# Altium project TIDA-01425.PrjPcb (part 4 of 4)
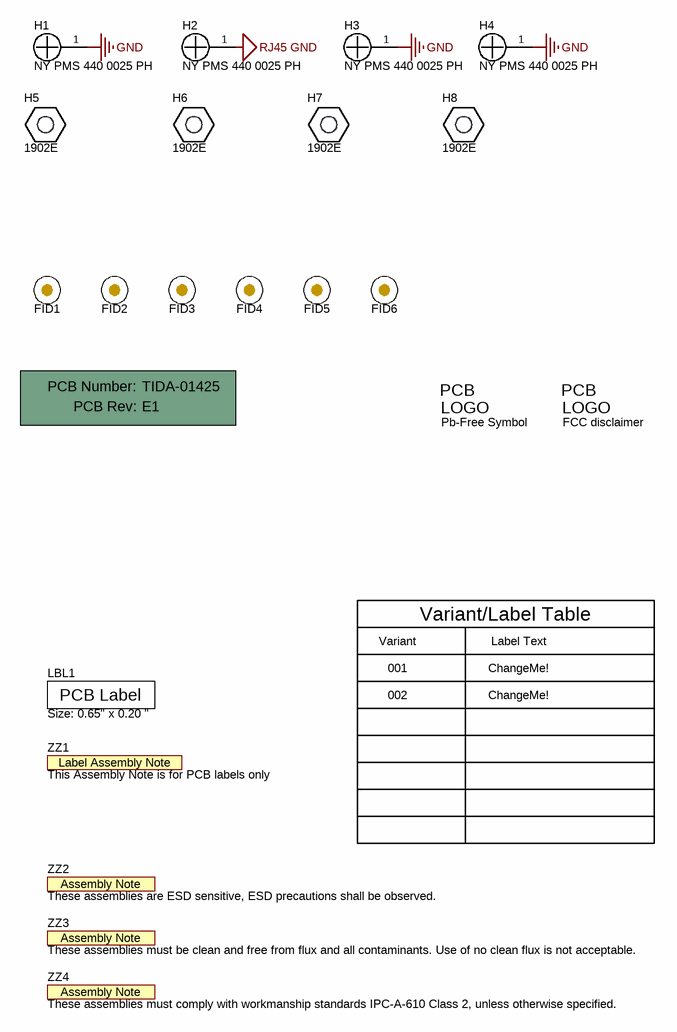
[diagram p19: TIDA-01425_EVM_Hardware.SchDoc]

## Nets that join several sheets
GND: DCDC PWR (37 pins), LP873x (PMIC) (47 pins), ANA PWR (40 pins), DIG PWR (148 pins), J6Entry (26 pins), J6E DDR (16 pins), DDR3 (74 pins), Ethernet_subsystem (48 pins), CAN_subsystem2.0 (24 pins), JTAG (9 pins), TIDA-01425_EVM_Hardware (H1.1 H3.1 H4.1)
RJ45 GND: Ethernet_subsystem (7 pins), TIDA-01425_EVM_Hardware (H2.1)
VDDS_1V8: LP873x (PMIC) (6 pins), DIG PWR (25 pins), J6Entry (U12.3)
BOARD_12V: DCDC PWR (12 pins), CAN_subsystem2.0 (J1.9)
DCAN1_RX: J6Entry (U13.H23), CAN_subsystem2.0 (CAN1_RX.1 U1.4 U3.4)
DCAN1_STB: J6Entry (U13.Y6), CAN_subsystem2.0 (R4.2)
DCAN1_TX: J6Entry (U13.H22), CAN_subsystem2.0 (CAN1_TX.1 U1.1 U3.1)
DCAN2_RX: J6Entry (U13.K22), CAN_subsystem2.0 (CAN2_RX.1 U2.4 U3.7)
DCAN2_STB: J6Entry (U13.K23), CAN_subsystem2.0 (R8.2)
DCAN2_TX: J6Entry (U13.H21), CAN_subsystem2.0 (CAN2_TX.1 U2.1 U3.6)
DDR EN: LP873x (PMIC) (R145.1 TP63.1 U26.10), J6E DDR (R69.2)
EMU_RSTn: J6Entry (R114.1), JTAG (J4.6 R52.1)
ENET_EN: J6Entry (U13.H5), Ethernet_subsystem (R34.2 U9.7)
ENET_INH: J6Entry (U13.G6), Ethernet_subsystem (U9.10)
ENET_INTSn: J6Entry (U13.L4), Ethernet_subsystem (U9.2)
ENET_WAKE: J6Entry (U13.G5), Ethernet_subsystem (R35.2 U9.8)
ETH_CLK0: J6Entry (R1.2), Ethernet_subsystem (U5.28)
ETH_CLK1: J6Entry (R19.2), Ethernet_subsystem (U9.5)
H_DDR1_A0: J6E DDR (R67.1 U13.AC18), DDR3 (U14.N3 U15.N3)
H_DDR1_A1: J6E DDR (R68.1 U13.AE19), DDR3 (U14.P7 U15.P7)
H_DDR1_A2: J6E DDR (R71.1 U13.AD19), DDR3 (U14.P3 U15.P3)
H_DDR1_A3: J6E DDR (R72.1 U13.AB19), DDR3 (U14.N2 U15.N2)
H_DDR1_A4: J6E DDR (R74.1 U13.AD20), DDR3 (U14.P8 U15.P8)
H_DDR1_A5: J6E DDR (R76.1 U13.AE20), DDR3 (U14.P2 U15.P2)
H_DDR1_A6: J6E DDR (R77.1 U13.AA18), DDR3 (U14.R8 U15.R8)
H_DDR1_A7: J6E DDR (R78.1 U13.AA20), DDR3 (U14.R2 U15.R2)
H_DDR1_A8: J6E DDR (R80.1 U13.Y21), DDR3 (U14.T8 U15.T8)
H_DDR1_A9: J6E DDR (R81.1 U13.AC20), DDR3 (U14.R3 U15.R3)
H_DDR1_A10: J6E DDR (R82.1 U13.AA21), DDR3 (U14.L7 U15.L7)
H_DDR1_A11: J6E DDR (R83.1 U13.AC21), DDR3 (U14.R7 U15.R7)
H_DDR1_A12: J6E DDR (R84.1 U13.AC22), DDR3 (U14.N7 U15.N7)
H_DDR1_BA0: J6E DDR (R85.1 U13.AE16), DDR3 (U14.M2 U15.M2)
H_DDR1_BA1: J6E DDR (R86.1 U13.AA16), DDR3 (U14.N8 U15.N8)
H_DDR1_BA2: J6E DDR (R87.1 U13.AB16), DDR3 (U14.M3 U15.M3)
H_DDR1_CASN: J6E DDR (R65.2 U13.AD16), DDR3 (U14.K3 U15.K3)
H_DDR1_CKE: J6E DDR (R62.1 U13.AB18), DDR3 (U14.K9 U15.K9)
H_DDR1_CLK_N: J6E DDR (R90.1 U13.AE21), DDR3 (U14.K7 U15.K7)
H_DDR1_CLK_P: J6E DDR (R89.1 U13.AD21), DDR3 (U14.J7 U15.J7)
H_DDR1_CSN0: J6E DDR (R63.1 U13.AC19), DDR3 (U14.L2 U15.L2)
H_DDR1_D0: J6E DDR (U13.AA23), DDR3 (U14.H7)
H_DDR1_D1: J6E DDR (U13.AC24), DDR3 (U14.F8)
H_DDR1_D2: J6E DDR (U13.AB24), DDR3 (U14.F7)
H_DDR1_D3: J6E DDR (U13.AD24), DDR3 (U14.H8)
H_DDR1_D4: J6E DDR (U13.AB23), DDR3 (U14.E3)
H_DDR1_D5: J6E DDR (U13.AC23), DDR3 (U14.H3)
H_DDR1_D6: J6E DDR (U13.AD23), DDR3 (U14.F2)
H_DDR1_D7: J6E DDR (U13.AE24), DDR3 (U14.G2)
H_DDR1_D8: J6E DDR (U13.AA24), DDR3 (U14.A2)
H_DDR1_D9: J6E DDR (U13.W25), DDR3 (U14.B8)
H_DDR1_D10: J6E DDR (U13.Y23), DDR3 (U14.A7)
H_DDR1_D11: J6E DDR (U13.AD25), DDR3 (U14.C8)
H_DDR1_D12: J6E DDR (U13.AC25), DDR3 (U14.C3)
H_DDR1_D13: J6E DDR (U13.AB25), DDR3 (U14.D7)
H_DDR1_D14: J6E DDR (U13.AA25), DDR3 (U14.A3)
H_DDR1_D15: J6E DDR (U13.W24), DDR3 (U14.C2)
H_DDR1_D16: J6E DDR (U13.W23), DDR3 (U15.F8)
H_DDR1_D17: J6E DDR (U13.U25), DDR3 (U15.H8)
H_DDR1_D18: J6E DDR (U13.U24), DDR3 (U15.F7)
H_DDR1_D19: J6E DDR (U13.W21), DDR3 (U15.F2)
H_DDR1_D20: J6E DDR (U13.T22), DDR3 (U15.E3)
H_DDR1_D21: J6E DDR (U13.U22), DDR3 (U15.G2)
H_DDR1_D22: J6E DDR (U13.U23), DDR3 (U15.H7)
H_DDR1_D23: J6E DDR (U13.T21), DDR3 (U15.H3)
H_DDR1_D24: J6E DDR (U13.T23), DDR3 (U15.C3)
H_DDR1_D25: J6E DDR (U13.T25), DDR3 (U15.A7)
H_DDR1_D26: J6E DDR (U13.T24), DDR3 (U15.B8)
H_DDR1_D27: J6E DDR (U13.P21), DDR3 (U15.A3)
H_DDR1_D28: J6E DDR (U13.N21), DDR3 (U15.C8)
H_DDR1_D29: J6E DDR (U13.P22), DDR3 (U15.C2)
H_DDR1_D30: J6E DDR (U13.P23), DDR3 (U15.A2)
H_DDR1_D31: J6E DDR (U13.P24), DDR3 (U15.D7)
H_DDR1_DQM0: J6E DDR (U13.AE23), DDR3 (U14.E7)
H_DDR1_DQM1: J6E DDR (U13.W22), DDR3 (U14.D3)
H_DDR1_DQM2: J6E DDR (U13.U21), DDR3 (U15.E7)
H_DDR1_DQM3: J6E DDR (U13.P25), DDR3 (U15.D3)
H_DDR1_DQS0_N: J6E DDR (U13.AE22), DDR3 (U14.G3)
H_DDR1_DQS0_P: J6E DDR (U13.AD22), DDR3 (U14.F3)
H_DDR1_DQS1_N: J6E DDR (U13.Y25), DDR3 (U14.B7)
H_DDR1_DQS1_P: J6E DDR (U13.Y24), DDR3 (U14.C7)
H_DDR1_DQS2_N: J6E DDR (U13.V25), DDR3 (U15.G3)
H_DDR1_DQS2_P: J6E DDR (U13.V24), DDR3 (U15.F3)
H_DDR1_DQS3_N: J6E DDR (U13.R25), DDR3 (U15.B7)
H_DDR1_DQS3_P: J6E DDR (U13.R24), DDR3 (U15.C7)
H_DDR1_ODT0: J6E DDR (R88.1 U13.AD18), DDR3 (U14.K1 U15.K1)
H_DDR1_RASN: J6E DDR (R64.2 U13.AD17), DDR3 (U14.J3 U15.J3)
H_DDR1_RST: J6E DDR (U13.AE17), DDR3 (U14.T2 U15.T2)
H_DDR1_WEN: J6E DDR (R66.1 U13.AE18), DDR3 (U14.L3 U15.L3)
H_EMU0: J6Entry (U13.C21), JTAG (J4.19 R54.1)
H_EMU1: J6Entry (U13.C22), JTAG (J4.21 R53.1)
H_EMU2: J6Entry (R133.2), JTAG (J4.13)
H_EMU3: J6Entry (U13.F14), JTAG (J4.17)
H_EMU4: J6Entry (U13.F13), JTAG (J4.23)
H_EMU5: J6Entry (U13.D8), JTAG (J4.25)
H_EMU6: J6Entry (U13.B7), JTAG (J4.27)
H_EMU7: J6Entry (U13.C7), JTAG (J4.29)
H_EMU8: J6Entry (U13.E8), JTAG (J4.31)
H_EMU9: J6Entry (U13.B8), JTAG (J4.33)
H_EMU10: J6Entry (U13.C8), JTAG (J4.35)
H_EMU11: J6Entry (U13.B9), JTAG (J4.37)
H_EMU12: J6Entry (U13.A7), JTAG (J4.39)
H_EMU13: J6Entry (U13.A9), JTAG (J4.41)
H_EMU14: J6Entry (U13.A8), JTAG (J4.43)
H_EMU15: J6Entry (U13.A11), JTAG (J4.45)
H_EMU16: J6Entry (U13.F10), JTAG (J4.47)
H_EMU17: J6Entry (U13.A10), JTAG (J4.49)
H_EMU18: J6Entry (U13.B10), JTAG (J4.51)
H_EMU19: J6Entry (U13.E10), JTAG (J4.53)
H_JTAG_RTCK: J6Entry (R134.2), JTAG (J4.7)
H_JTAG_TCK: J6Entry (U13.K21), JTAG (J4.3 R55.1)
H_JTAG_TDI: J6Entry (U13.L23), JTAG (J4.5)
H_JTAG_TDO: J6Entry (R135.2), JTAG (J4.4)
H_JTAG_TMS: J6Entry (U13.L21), JTAG (J4.2 R51.1)
H_JTAG_TRSTn: J6Entry (U13.L22), JTAG (R56.1 R57.1)
H_PMIC_INT: LP873x (PMIC) (R91.1 TP57.1 U25.9 U26.9), J6Entry (U13.AB10)
H_PORZ: LP873x (PMIC) (5 pins), J6Entry (U13.F19), Ethernet_subsystem (U5.23 U9.3)
I2C_SCL: LP873x (PMIC) (TP56.1 U25.17 U26.17), J6Entry (R131.1 U13.G22)
I2C_SDA: LP873x (PMIC) (TP55.1 U25.18 U26.18), J6Entry (R132.1 U13.G23)
MDC: J6Entry (U13.D10), Ethernet_subsystem (U5.25 U9.1)
MDIO: J6Entry (U13.C10), Ethernet_subsystem (R2.1 R18.1 U5.24 U9.36)
MII0_COL: J6Entry (U13.L5), Ethernet_subsystem (R20.1)
MII0_CRS: J6Entry (U13.P4), Ethernet_subsystem (R136.1)
MII0_RX_CLK: J6Entry (U13.N6), Ethernet_subsystem (R137.1)
MII0_RX_D0: J6Entry (U13.R1), Ethernet_subsystem (R138.1)
MII0_RX_D1: J6Entry (U13.R2), Ethernet_subsystem (R139.1)
MII0_RX_D2: J6Entry (U13.T5), Ethernet_subsystem (R140.1)
MII0_RX_D3: J6Entry (U13.T4), Ethernet_subsystem (R141.1)
MII0_RX_DV: J6Entry (U13.N5), Ethernet_subsystem (R143.1)
MII0_RX_ER: J6Entry (U13.P3), Ethernet_subsystem (R142.1)
MII0_TX_CLK: J6Entry (U13.N2), Ethernet_subsystem (R17.1)
MII0_TX_D0: J6Entry (U13.N4), Ethernet_subsystem (U5.4)
MII0_TX_D1: J6Entry (U13.N3), Ethernet_subsystem (U5.5)
MII0_TX_D2: J6Entry (U13.N1), Ethernet_subsystem (U5.6)
MII0_TX_D3: J6Entry (U13.P2), Ethernet_subsystem (U5.7)
MII0_TX_EN: J6Entry (U13.P1), Ethernet_subsystem (U5.3)
PMIC EN: DCDC PWR (R60.1 TP19.1 U17.19), LP873x (PMIC) (U25.6 U26.6)
RX_CLK_1: J6Entry (U13.E11), Ethernet_subsystem (R29.1)
RX_CTRL_1: J6Entry (U13.F11), Ethernet_subsystem (U9.15)
RX_D0_1: J6Entry (U13.D13), Ethernet_subsystem (U9.26)
RX_D1_1: J6Entry (U13.C13), Ethernet_subsystem (R9.1 U9.25)
RX_D2_1: J6Entry (U13.E13), Ethernet_subsystem (R147.1 U9.24)
RX_D3_1: J6Entry (U13.B13), Ethernet_subsystem (U9.23)
SW_3V3: LP873x (PMIC) (6 pins), DIG PWR (32 pins), J6Entry (23 pins), Ethernet_subsystem (38 pins), CAN_subsystem2.0 (C252.1 C253.1 R3.2 R146.2)
SYS_3V3: DCDC PWR (14 pins), LP873x (PMIC) (34 pins), J6E DDR (C184.1 R70.2 U19.10), JTAG (7 pins)
SYS_5V0: DCDC PWR (5 pins), LP873x (PMIC) (5 pins), CAN_subsystem2.0 (7 pins)
TX_CLK_1: J6Entry (U13.B11), Ethernet_subsystem (R25.1)
TX_CTRL_1: J6Entry (U13.D11), Ethernet_subsystem (U9.29)
TX_D0_1: J6Entry (U13.A13), Ethernet_subsystem (U9.33)
TX_D1_1: J6Entry (U13.A12), Ethernet_subsystem (U9.32)
TX_D2_1: J6Entry (U13.B12), Ethernet_subsystem (U9.31)
TX_D3_1: J6Entry (U13.C11), Ethernet_subsystem (U9.30)
VDA_PHY_1V8: LP873x (PMIC) (C268.1 TP62.1 U26.7), ANA PWR (7 pins)
VDA_PLL_1V8: LP873x (PMIC) (C267.1 TP61.1 U26.1), ANA PWR (8 pins)
VDA_USB_3V3: LP873x (PMIC) (C250.1 TP54.1 U25.7), ANA PWR (5 pins)
VDD_CORE_AVS: LP873x (PMIC) (C240.1 L2.2 TP51.1 U25.2), DIG PWR (53 pins)
VDD_DDR_1V35: LP873x (PMIC) (C263.1 L14.2 TP60.1 U26.3), DIG PWR (20 pins), J6E DDR (14 pins), DDR3 (66 pins)
VDD_DSP_AVS: LP873x (PMIC) (C244.1 L12.2 TP53.1 U25.3), DIG PWR (19 pins)
VDDR_VREF: J6E DDR (C190.1 U13.Y20 U19.6), DDR3 (8 pins)

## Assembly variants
001: not fitted C194 C222 C228 C229 C241 C242 C251 C257 C260 C261 C271 FID1 FID2 FID3 FID4 FID5 FID6 R2 R4 R8 R9 R43 R45 R47 R56 R96 R102 R106 R110 R115 R120 R148 U3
